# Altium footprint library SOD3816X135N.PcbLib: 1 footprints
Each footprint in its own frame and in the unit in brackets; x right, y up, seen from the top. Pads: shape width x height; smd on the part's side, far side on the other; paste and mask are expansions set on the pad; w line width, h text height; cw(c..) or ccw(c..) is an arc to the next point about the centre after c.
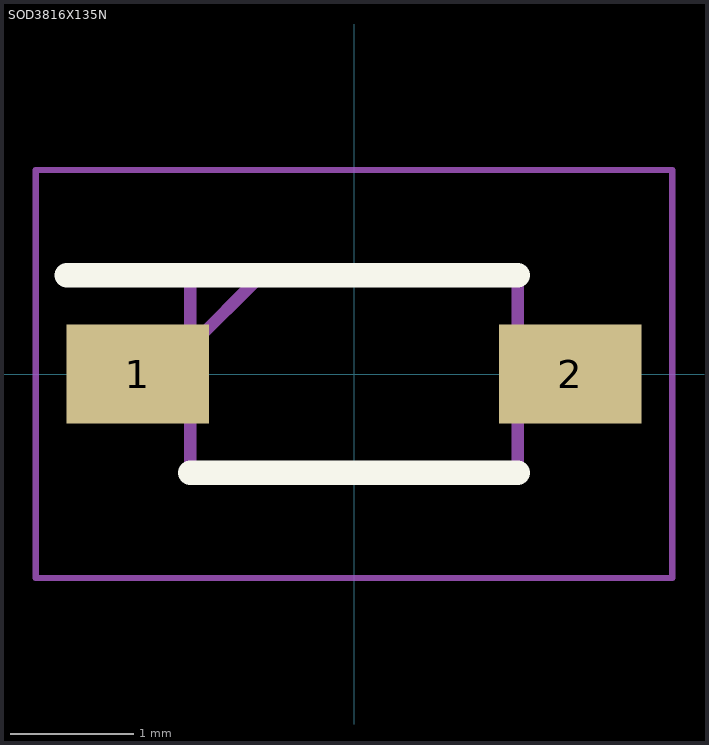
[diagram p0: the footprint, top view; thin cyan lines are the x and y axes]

## SOD3816X135N [mm]
pads (2):
  rect 1.15x0.8 smd: 1(-1.75,0) 2(1.75,0)
Top Overlay:
  lines w0.2: -2.325,0.8 1.325,0.8 ; -1.325,-0.8 1.325,-0.8
Mechanical 15:
  lines w0.1: -1.325,0.225 -0.75,0.8 ; -1.325,-0.8 1.325,-0.8 1.325,0.8 -1.325,0.8 -1.325,-0.8
Mechanical 20:
  lines w0.05: -2.575,-1.65 2.575,-1.65 2.575,1.65 -2.575,1.65 -2.575,-1.65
